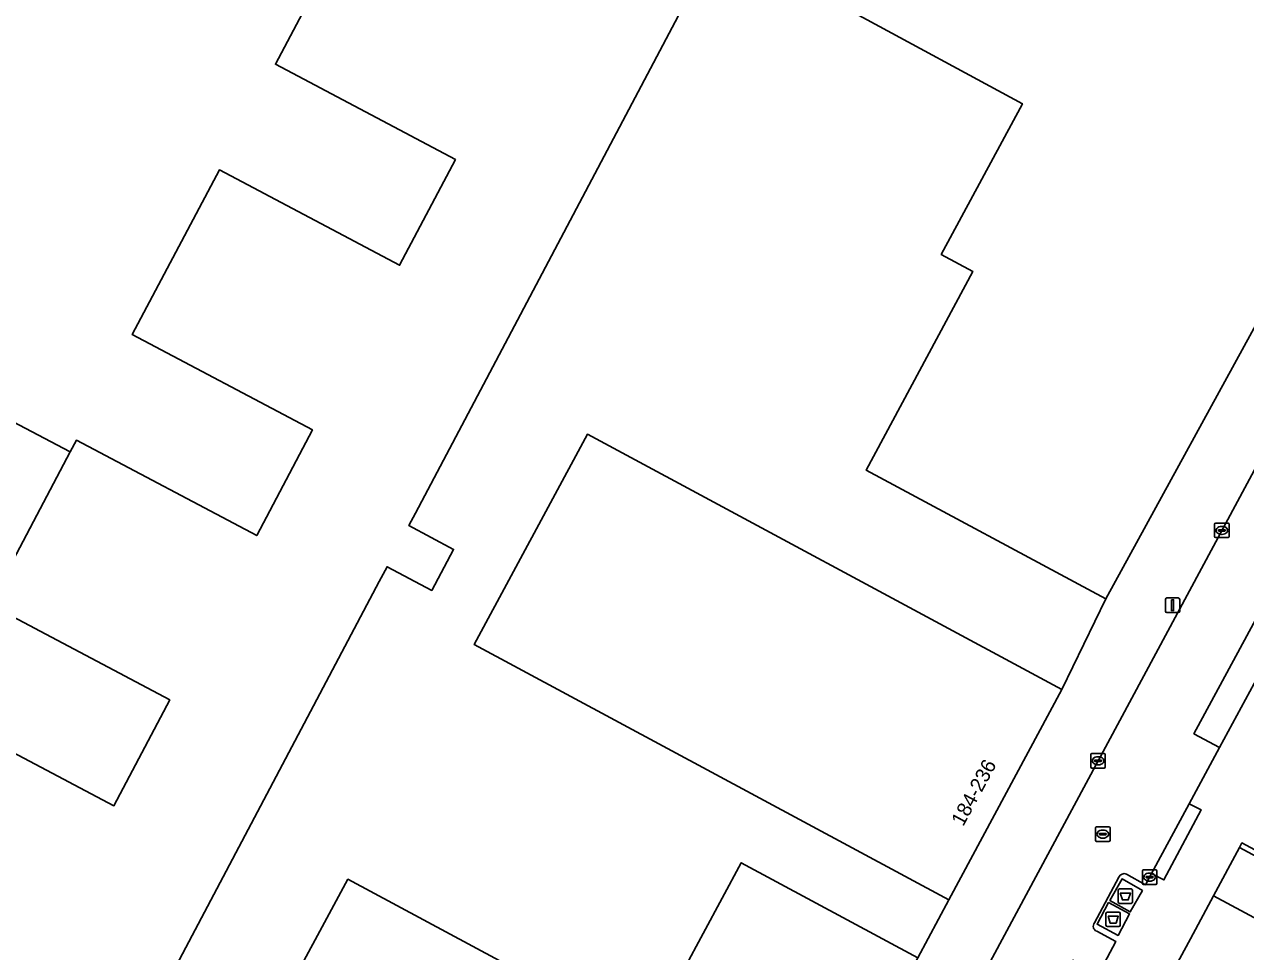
# Model space of a CAD drawing. Extents: x 159489 to 160304, y 383825 to 384531.
# Drawn here: x 159684.5 to 159768.9, y 384107.2 to 384171.2 of the extents above; entities that cross this region are included whole.
import ezdxf

# ---------------------------------------------------------------- set-up
doc = ezdxf.new("R2010")
doc.units = 0
for name, color, linetype in [('IMGEO_Afval_apart_plaats', 7, 'Continuous'), ('IMGEO_Kolk', 7, 'Continuous'), ('IMGEO_Lichtmast', 7, 'Continuous'), ('IMGEO_Muur', 7, 'Continuous'), ('IMGEO_Pand', 7, 'Continuous'), ('IMGEO_Pand_nummerreeks', 7, 'Continuous'), ('IMGEO_Parkeervlak_gesloten', 7, 'Continuous'), ('IMGEO_Rijbaan_lokaal_gesloten', 7, 'Continuous'), ('IMGEO_Rioolput', 7, 'Continuous'), ('IMGEO_Voetpad_gesloten', 7, 'Continuous'), ('IMGEO_Voetpad_open', 7, 'Continuous')]:
    doc.layers.add(name, color=color, linetype=linetype)

msp = doc.modelspace()

# ---------------------------------------------------------------- linework, layer by layer
at = {"layer": 'IMGEO_Afval_apart_plaats'}
for p, q in [((159760.072, 384110.598), (159760.072, 384111.398)), ((159760.072, 384111.398), (159760.072, 384110.598)), ((159760.172, 384111.498), (159760.962, 384111.498)), ((159760.962, 384111.498), (159760.172, 384111.498)), ((159761.062, 384111.398), (159761.062, 384110.598)), ((159761.062, 384110.598), (159761.062, 384111.398)), ((159760.962, 384110.498), (159760.172, 384110.498)), ((159760.172, 384110.498), (159760.962, 384110.498)), ((159759.224, 384108.993), (159759.224, 384109.793)), ((159759.224, 384109.793), (159759.224, 384108.993)), ((159759.324, 384109.893), (159760.114, 384109.893)), ((159760.114, 384109.893), (159759.324, 384109.893)), ((159760.214, 384109.793), (159760.214, 384108.993)), ((159760.214, 384108.993), (159760.214, 384109.793)), ((159760.114, 384108.893), (159759.324, 384108.893)), ((159759.324, 384108.893), (159760.114, 384108.893))]:
    msp.add_line(p, q, dxfattribs=at)
for points in [[(159760.215, 384111.212), (159760.919, 384111.212), (159760.77, 384110.742), (159760.364, 384110.742), (159760.215, 384111.212)], [(159759.367, 384109.607), (159760.071, 384109.607), (159759.922, 384109.137), (159759.516, 384109.137), (159759.367, 384109.607)]]:
    msp.add_lwpolyline(points, dxfattribs=at)
for centre, start, end in [((159760.172, 384111.398), 90, 180), ((159760.172, 384111.398), 90, 180), ((159760.962, 384111.398), 0, 90), ((159760.962, 384111.398), 360, 90), ((159760.172, 384110.598), 180, 270), ((159760.172, 384110.598), 180, 270), ((159760.962, 384110.598), 270, 0), ((159760.962, 384110.598), 270, 0), ((159759.324, 384109.793), 90, 180), ((159759.324, 384109.793), 90, 180), ((159760.114, 384109.793), 0, 90), ((159760.114, 384109.793), 360, 90), ((159759.324, 384108.993), 180, 270), ((159759.324, 384108.993), 180, 270), ((159760.114, 384108.993), 270, 0), ((159760.114, 384108.993), 270, 0)]:
    msp.add_arc(centre, 0.1, start, end, dxfattribs=at)
at = {"layer": 'IMGEO_Kolk'}
for p, q in [((159766.73, 384135.832), (159766.73, 384136.684)), ((159766.805, 384136.758), (159767.657, 384136.758)), ((159767.218, 384136.538), (159767.243, 384136.538)), ((159767.731, 384136.684), (159767.731, 384135.832)), ((159767.657, 384135.758), (159766.805, 384135.758)), ((159766.989, 384136.252), (159766.989, 384136.264)), ((159767.427, 384136.215), (159767.029, 384136.215)), ((159767.032, 384136.301), (159767.43, 384136.301)), ((159767.241, 384135.978), (159767.216, 384135.978)), ((159767.473, 384136.264), (159767.473, 384136.252)), ((159758.18, 384119.92), (159758.18, 384120.772)), ((159758.255, 384120.846), (159759.107, 384120.846)), ((159758.439, 384120.34), (159758.439, 384120.352)), ((159758.482, 384120.389), (159758.88, 384120.389)), ((159758.668, 384120.626), (159758.693, 384120.626)), ((159758.923, 384120.352), (159758.923, 384120.34)), ((159759.181, 384120.772), (159759.181, 384119.92)), ((159759.107, 384119.846), (159758.255, 384119.846)), ((159758.877, 384120.303), (159758.479, 384120.303)), ((159758.691, 384120.066), (159758.666, 384120.066)), ((159761.815, 384112.813), (159762.667, 384112.813)), ((159761.74, 384111.887), (159761.74, 384112.739)), ((159761.999, 384112.307), (159761.999, 384112.319)), ((159762.437, 384112.27), (159762.039, 384112.27)), ((159762.042, 384112.356), (159762.44, 384112.356)), ((159762.251, 384112.033), (159762.226, 384112.033)), ((159762.228, 384112.593), (159762.253, 384112.593)), ((159762.483, 384112.319), (159762.483, 384112.307)), ((159762.741, 384112.739), (159762.741, 384111.887)), ((159762.667, 384111.813), (159761.815, 384111.813))]:
    msp.add_line(p, q, dxfattribs=at)
for points in [[(159766.73, 384135.832), (159766.73, 384136.684)], [(159766.805, 384136.758), (159767.657, 384136.758)], [(159767.731, 384136.684), (159767.731, 384135.832)], [(159767.657, 384135.758), (159766.805, 384135.758)], [(159758.18, 384119.92), (159758.18, 384120.772)], [(159758.255, 384120.846), (159759.107, 384120.846)], [(159759.181, 384120.772), (159759.181, 384119.92)], [(159759.107, 384119.846), (159758.255, 384119.846)], [(159761.815, 384112.813), (159762.667, 384112.813)], [(159761.74, 384111.887), (159761.74, 384112.739)], [(159762.741, 384112.739), (159762.741, 384111.887)], [(159762.667, 384111.813), (159761.815, 384111.813)]]:
    msp.add_lwpolyline(points, dxfattribs=at)
for centre, radius, start, end in [((159766.807, 384136.682), 0.0765, 91.55205, 178.44795), ((159766.807, 384136.682), 0.0765, 91.55205, 178.44795), ((159767.655, 384136.682), 0.0765, 1.55205, 88.44795), ((159767.655, 384136.682), 0.0765, 1.55205, 88.44795), ((159766.807, 384135.834), 0.0765, 181.55205, 268.44795), ((159766.807, 384135.834), 0.0765, 181.55205, 268.44795), ((159767.029, 384136.261), 0.0403, 85.87752, 175.75265), ((159767.026, 384136.251), 0.0366, 178.93798, 274.71019), ((159767.43, 384136.258), 0.043, 264.86636, 352.45326), ((159767.434, 384136.263), 0.0386, 1.73085, 96.63898), ((159767.655, 384135.834), 0.0765, 271.55205, 358.44795), ((159767.655, 384135.834), 0.0765, 271.55205, 358.44795), ((159758.257, 384120.77), 0.0765, 91.55205, 178.44795), ((159758.257, 384120.77), 0.0765, 91.55205, 178.44795), ((159758.479, 384120.349), 0.0403, 85.87752, 175.75265), ((159758.476, 384120.339), 0.0366, 178.93798, 274.71019), ((159758.88, 384120.346), 0.043, 264.86636, 352.45326), ((159758.884, 384120.351), 0.0386, 1.73085, 96.63898), ((159759.105, 384120.77), 0.0765, 1.55205, 88.44795), ((159759.105, 384120.77), 0.0765, 1.55205, 88.44795), ((159758.257, 384119.922), 0.0765, 181.55205, 268.44795), ((159758.257, 384119.922), 0.0765, 181.55205, 268.44795), ((159759.105, 384119.922), 0.0765, 271.55205, 358.44795), ((159759.105, 384119.922), 0.0765, 271.55205, 358.44795), ((159761.817, 384112.737), 0.0765, 91.55205, 178.44795), ((159761.817, 384112.737), 0.0765, 91.55205, 178.44795), ((159762.665, 384112.737), 0.0765, 1.55205, 88.44795), ((159762.665, 384112.737), 0.0765, 1.55205, 88.44795), ((159762.039, 384112.316), 0.0403, 85.87752, 175.75265), ((159762.036, 384112.306), 0.0366, 178.93798, 274.71019), ((159762.44, 384112.313), 0.043, 264.86636, 352.45326), ((159762.444, 384112.318), 0.0386, 1.73085, 96.63898), ((159761.817, 384111.889), 0.0765, 181.55205, 268.44795), ((159761.817, 384111.889), 0.0765, 181.55205, 268.44795), ((159762.665, 384111.889), 0.0765, 271.55205, 358.44795), ((159762.665, 384111.889), 0.0765, 271.55205, 358.44795)]:
    msp.add_arc(centre, radius, start, end, dxfattribs=at)
for centre, major_axis, ratio, start_param, end_param in [((159767.217, 384136.258), (-0.387, 0.002), 0.722429, 4.712389, 7.853982), ((159767.242, 384136.258), (-0.39, 0.002), 0.717154, 1.570796, 4.712389), ((159758.667, 384120.346), (-0.387, 0.002), 0.722429, 4.712389, 7.853982), ((159758.692, 384120.346), (-0.39, 0.002), 0.717154, 1.570796, 4.712389), ((159762.227, 384112.313), (-0.387, 0.002), 0.722429, 4.712389, 7.853982), ((159762.252, 384112.313), (-0.39, 0.002), 0.717154, 1.570796, 4.712389)]:
    msp.add_ellipse(centre, major_axis=major_axis, ratio=ratio, start_param=start_param, end_param=end_param, dxfattribs=at)
at = {"layer": 'IMGEO_Lichtmast'}
for p, q in [((159763.328, 384130.69), (159763.328, 384131.49)), ((159763.328, 384131.49), (159763.328, 384130.69)), ((159763.428, 384131.59), (159764.218, 384131.59)), ((159764.218, 384131.59), (159763.428, 384131.59)), ((159764.318, 384131.49), (159764.318, 384130.69)), ((159764.318, 384130.69), (159764.318, 384131.49)), ((159764.218, 384130.59), (159763.428, 384130.59)), ((159763.428, 384130.59), (159764.218, 384130.59))]:
    msp.add_line(p, q, dxfattribs=at)
msp.add_lwpolyline([(159763.748, 384131.465), (159763.898, 384131.465), (159763.898, 384130.715), (159763.748, 384130.715), (159763.748, 384131.465)], dxfattribs=at)
for centre, start, end in [((159763.428, 384131.49), 90, 180), ((159763.428, 384131.49), 90, 180), ((159764.218, 384131.49), 0, 90), ((159764.218, 384131.49), 360, 90), ((159763.428, 384130.69), 180, 270), ((159763.428, 384130.69), 180, 270), ((159764.218, 384130.69), 270, 0), ((159764.218, 384130.69), 270, 0)]:
    msp.add_arc(centre, 0.1, start, end, dxfattribs=at)
at = {"layer": 'IMGEO_Muur'}
msp.add_lwpolyline([(159768.906, 384114.514), (159768.611, 384114.673), (159768.446, 384114.365), (159776.835, 384109.843), (159777.002, 384110.151), (159770.147, 384113.845)], close=True, dxfattribs=at)
at = {"layer": 'IMGEO_Pand'}
for points in [[(159661.097, 384155.654), (159687.696, 384141.679), (159688.119, 384142.479), (159700.579, 384135.9), (159704.42, 384143.2), (159691.98, 384149.78), (159698, 384161.15), (159710.44, 384154.57), (159714.299, 384161.869), (159701.859, 384168.45), (159707.869, 384179.82), (159720.309, 384173.25), (159721.988, 384176.427), (159706.924, 384184.426), (159717.909, 384205.131), (159698.141, 384215.619), (159696.5, 384212.654), (159692.377, 384214.788), (159694.017, 384217.753)], [(159691.579, 384099.696), (159709.034, 384132.721), (159709.579, 384133.752), (159712.659, 384132.11), (159714.168, 384134.941), (159711.071, 384136.599), (159711.529, 384137.442), (159729.91, 384172.22), (159721.988, 384176.427), (159720.309, 384173.25), (159707.869, 384179.82), (159701.859, 384168.45), (159714.299, 384161.869), (159710.44, 384154.57), (159698, 384161.15), (159691.98, 384149.78), (159704.42, 384143.2), (159700.579, 384135.9), (159688.119, 384142.479), (159687.696, 384141.679), (159682.119, 384131.13), (159694.57, 384124.549), (159690.709, 384117.239), (159678.25, 384123.82)]]:
    msp.add_lwpolyline(points, dxfattribs=at)
for points in [[(159781.081, 384171.509), (159760.006, 384182.817), (159759.86, 384182.554), (159751.335, 384187.138), (159749.801, 384186.691), (159741.891, 384171.976), (159753.455, 384165.727), (159747.85, 384155.324), (159750.036, 384154.135), (159742.655, 384140.419), (159759.218, 384131.522), (159770.883, 384152.856), (159769.847, 384153.424), (159771.281, 384156.067), (159772.985, 384156.701)], [(159723.412, 384142.894), (159715.597, 384128.371), (159748.367, 384110.748), (159756.188, 384125.276)], [(159706.87, 384112.163), (159701.898, 384102.938), (159698.331, 384104.838), (159694.71, 384098.068), (159731.054, 384078.532), (159738.835, 384092.992), (159730.115, 384097.685), (159733.403, 384103.792), (159742.122, 384099.1), (159746.233, 384106.739), (159734.04, 384113.305), (159727.463, 384101.093)], [(159780.079, 384103.825), (159766.66, 384111.026), (159765.061, 384108.041), (159763.74, 384105.588), (159763.585, 384104.945), (159761.091, 384100.297), (159760.941, 384100.377), (159757.19, 384093.409), (159767.715, 384087.664), (159768.398, 384087.297), (159771.882, 384093.775), (159773.584, 384092.86), (159774.052, 384092.608), (159774.383, 384093.224)]]:
    msp.add_lwpolyline(points, close=True, dxfattribs=at)
at = {"layer": 'IMGEO_Parkeervlak_gesloten'}
msp.add_lwpolyline([(159775.147, 384136.187), (159773.371, 384137.146), (159765.302, 384122.213), (159767.077, 384121.254)], close=True, dxfattribs=at)
at = {"layer": 'IMGEO_Rijbaan_lokaal_gesloten'}
for points in [[(159785.842, 384170.895), (159785.06, 384169.44), (159732.135, 384070.941), (159724.587, 384056.893), (159731.166, 384054.292), (159733.379, 384058.49), (159735.26, 384062.057), (159733.476, 384062.998), (159733.684, 384063.394), (159756.933, 384106.574), (159758.71, 384105.618), (159759.915, 384107.857), (159758.589, 384108.571)], [(159764.983, 384117.379), (159767.077, 384121.254), (159765.302, 384122.213), (159773.371, 384137.146), (159775.147, 384136.187), (159776.629, 384138.93), (159774.854, 384139.889), (159777.432, 384144.66), (159779.207, 384143.701), (159782.562, 384149.935), (159784.449, 384153.458), (159782.671, 384154.411), (159787.869, 384164.115), (159789.648, 384163.162), (159791.147, 384165.96), (159791.589, 384166.785)], [(159760.639, 384112.524), (159761.954, 384111.781), (159762.373, 384112.557), (159764.983, 384117.379)], [(159758.424, 384109.152), (159760.115, 384112.313)]]:
    msp.add_lwpolyline(points, dxfattribs=at)
for centre, radius, start, end in [((159760.488, 384112.142), 0.41, 68.45395, 155.41256), ((159758.726, 384108.924), 0.378, 142.92245, 248.78591)]:
    msp.add_arc(centre, radius, start, end, dxfattribs=at)
at = {"layer": 'IMGEO_Rioolput'}
for p, q in [((159758.506, 384114.858), (159758.506, 384115.71)), ((159758.581, 384115.784), (159759.433, 384115.784)), ((159758.765, 384115.278), (159758.765, 384115.29)), ((159758.808, 384115.327), (159759.206, 384115.327)), ((159758.994, 384115.564), (159759.019, 384115.564)), ((159759.249, 384115.29), (159759.249, 384115.278)), ((159759.507, 384115.71), (159759.507, 384114.858)), ((159759.433, 384114.784), (159758.581, 384114.784)), ((159759.203, 384115.241), (159758.805, 384115.241)), ((159759.017, 384115.004), (159758.992, 384115.004))]:
    msp.add_line(p, q, dxfattribs=at)
for points in [[(159758.506, 384114.858), (159758.506, 384115.71)], [(159758.581, 384115.784), (159759.433, 384115.784)], [(159759.507, 384115.71), (159759.507, 384114.858)], [(159759.433, 384114.784), (159758.581, 384114.784)]]:
    msp.add_lwpolyline(points, dxfattribs=at)
for centre, radius, start, end in [((159758.583, 384115.708), 0.0765, 91.55205, 178.44795), ((159758.583, 384115.708), 0.0765, 91.55205, 178.44795), ((159758.805, 384115.287), 0.0403, 85.87752, 175.75265), ((159758.802, 384115.277), 0.0366, 178.93798, 274.71019), ((159759.206, 384115.284), 0.043, 264.86636, 352.45326), ((159759.21, 384115.289), 0.0386, 1.73085, 96.63898), ((159759.431, 384115.708), 0.0765, 1.55205, 88.44795), ((159759.431, 384115.708), 0.0765, 1.55205, 88.44795), ((159758.583, 384114.86), 0.0765, 181.55205, 268.44795), ((159758.583, 384114.86), 0.0765, 181.55205, 268.44795), ((159759.431, 384114.86), 0.0765, 271.55205, 358.44795), ((159759.431, 384114.86), 0.0765, 271.55205, 358.44795)]:
    msp.add_arc(centre, radius, start, end, dxfattribs=at)
for centre, major_axis, ratio, start_param, end_param in [((159758.993, 384115.284), (-0.387, 0.002), 0.722429, 4.712389, 7.853982), ((159759.018, 384115.284), (-0.39, 0.002), 0.717154, 1.570796, 4.712389)]:
    msp.add_ellipse(centre, major_axis=major_axis, ratio=ratio, start_param=start_param, end_param=end_param, dxfattribs=at)
at = {"layer": 'IMGEO_Voetpad_gesloten'}
for points in [[(159761.744, 384111.387), (159760.336, 384112.187), (159759.496, 384110.708), (159760.904, 384109.908)], [(159760.862, 384109.774), (159759.41, 384110.549), (159758.616, 384109.061), (159760.068, 384108.286)]]:
    msp.add_lwpolyline(points, close=True, dxfattribs=at)
at = {"layer": 'IMGEO_Voetpad_open'}
for points in [[(159729.91, 384172.22), (159711.529, 384137.442), (159711.071, 384136.599), (159714.168, 384134.941), (159712.659, 384132.11), (159709.579, 384133.752), (159709.034, 384132.721), (159691.579, 384099.696)], [(159701.898, 384102.938), (159706.87, 384112.163), (159727.463, 384101.093), (159734.04, 384113.305), (159746.233, 384106.739), (159748.367, 384110.748), (159715.597, 384128.371), (159723.412, 384142.894), (159756.188, 384125.276), (159759.218, 384131.522), (159742.655, 384140.419), (159750.036, 384154.135), (159747.85, 384155.324), (159753.455, 384165.727), (159741.891, 384171.976)], [(159775.147, 384136.187), (159767.077, 384121.254), (159764.983, 384117.379), (159765.797, 384116.969), (159763.224, 384112.124), (159762.373, 384112.557), (159761.954, 384111.781), (159760.639, 384112.524)], [(159750.647, 384078.705), (159753.203, 384083.461), (159755.588, 384087.9), (159754.532, 384088.469), (159757.19, 384093.409), (159760.941, 384100.377), (159761.091, 384100.297), (159763.585, 384104.945), (159763.74, 384105.588), (159765.061, 384108.041), (159766.66, 384111.026), (159768.446, 384114.365), (159768.611, 384114.673), (159768.906, 384114.514)], [(159776.835, 384109.843), (159768.446, 384114.365), (159766.66, 384111.026), (159780.079, 384103.825)], [(159760.115, 384112.313), (159758.424, 384109.152)], [(159758.589, 384108.571), (159759.915, 384107.857), (159758.71, 384105.618), (159735.465, 384062.445), (159735.26, 384062.057), (159733.379, 384058.49), (159737.293, 384056.412), (159744.543, 384069.861), (159745.606, 384069.324), (159748.091, 384073.948), (159750.647, 384078.705)]]:
    msp.add_lwpolyline(points, dxfattribs=at)
for points in [[(159785.06, 384169.44), (159781.081, 384171.509), (159772.985, 384156.701), (159771.281, 384156.067), (159769.847, 384153.424), (159770.883, 384152.856), (159759.218, 384131.522), (159756.188, 384125.276), (159748.367, 384110.748), (159746.233, 384106.739), (159742.122, 384099.1), (159733.403, 384103.792), (159730.115, 384097.685), (159738.835, 384092.992), (159731.054, 384078.532), (159694.71, 384098.068), (159691.579, 384099.696), (159688.581, 384094.024), (159727.344, 384073.348), (159727.4, 384073.454), (159732.135, 384070.941)], [(159678.25, 384123.82), (159690.709, 384117.239), (159694.57, 384124.549), (159682.119, 384131.13), (159687.696, 384141.679), (159661.097, 384155.654), (159640.799, 384117.299), (159641.726, 384116.807), (159642.659, 384118.574), (159642.924, 384118.433), (159642.974, 384118.53), (159674.217, 384102.022), (159674.165, 384101.923), (159674.429, 384101.789), (159673.691, 384100.384), (159680.029, 384097.039), (159684.69, 384105.859), (159672.239, 384112.45)], [(159762.373, 384112.557), (159763.224, 384112.124), (159765.797, 384116.969), (159764.983, 384117.379)], [(159759.496, 384110.708), (159760.336, 384112.187), (159761.744, 384111.387), (159760.904, 384109.908)], [(159758.616, 384109.061), (159759.41, 384110.549), (159760.862, 384109.774), (159760.068, 384108.286)]]:
    msp.add_lwpolyline(points, close=True, dxfattribs=at)
for centre, radius, start, end in [((159760.488, 384112.142), 0.41, 68.45395, 155.41256), ((159758.726, 384108.924), 0.378, 142.92245, 248.78591)]:
    msp.add_arc(centre, radius, start, end, dxfattribs=at)

# ---------------------------------------------------------------- texts
at = {"layer": 'IMGEO_Pand_nummerreeks'}
msp.add_text('184-236', height=1, rotation=61.70182, dxfattribs=at).set_placement((159749.366, 384115.769))

doc.saveas('drawing.dxf')
